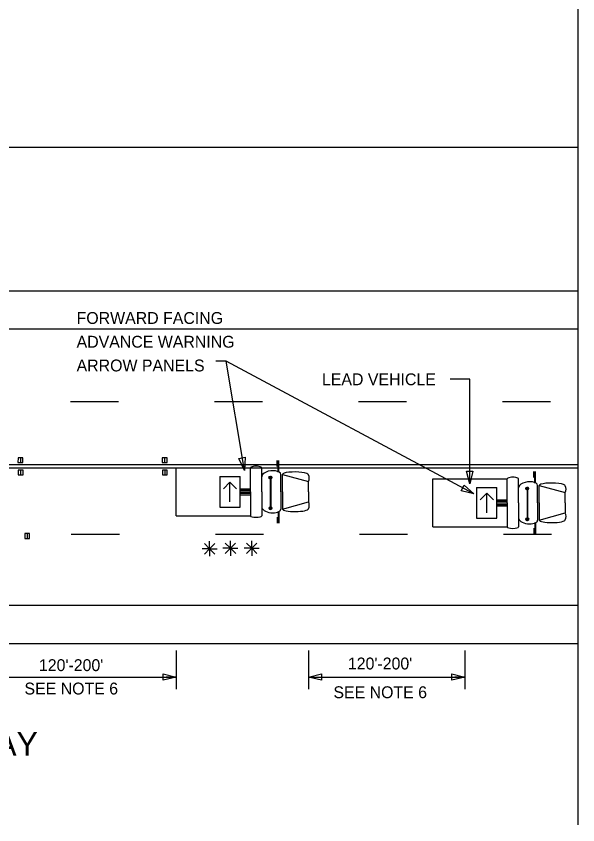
# Model space of a CAD drawing. Extents: x 1373848 to 1374003, y 380642 to 381248.
# Drawn here: x 1373899.76 to 1373928.12, y 380977.04 to 381017.9 of the extents above; entities that cross this region are included whole.
import ezdxf

# ---------------------------------------------------------------- set-up
doc = ezdxf.new("R2010")
doc.units = 0
doc.layers.add('Working Level 1', color=7, linetype='Continuous')

msp = doc.modelspace()

# ---------------------------------------------------------------- linework, layer by layer
at = {"layer": 'Working Level 1'}
for p, q in [((1373928.123, 381081.277), (1373928.123, 380977.045)), ((1373848.144, 381011.273), (1373928.089, 381011.273)), ((1373875.816, 381004.029), (1373928.123, 381004.029)), ((1373875.274, 381002.105), (1373928.123, 381002.105)), ((1373922.876, 380993.763), (1373910.36, 381000.464)), ((1373875.372, 380995.257), (1373928.123, 380995.257)), ((1373899.852, 380995.587), (1373899.851, 380995.344)), ((1373899.851, 380995.344), (1373900.094, 380995.344)), ((1373900.094, 380995.587), (1373899.852, 380995.587)), ((1373899.973, 380995.587), (1373899.973, 380995.344)), ((1373900.094, 380995.344), (1373900.094, 380995.587)), ((1373907.378, 380995.587), (1373907.135, 380995.587)), ((1373907.135, 380995.587), (1373907.135, 380995.344)), ((1373907.135, 380995.344), (1373907.378, 380995.344)), ((1373907.257, 380995.587), (1373907.257, 380995.344)), ((1373907.378, 380995.344), (1373907.378, 380995.587)), ((1373912.937, 380995.156), (1373912.937, 380995.453)), ((1373912.984, 380994.87), (1373912.984, 380995.453)), ((1373913.024, 380994.87), (1373913.024, 380995.453)), ((1373916.859, 380995.257), (1373928.123, 380995.257)), ((1373875.406, 380995.089), (1373928.123, 380995.089)), ((1373900.105, 380994.97), (1373899.862, 380994.97)), ((1373899.862, 380994.97), (1373899.862, 380994.727)), ((1373899.984, 380994.97), (1373899.984, 380994.727)), ((1373900.105, 380994.727), (1373900.105, 380994.97)), ((1373907.389, 380994.97), (1373907.146, 380994.97)), ((1373907.146, 380994.97), (1373907.146, 380994.727)), ((1373907.268, 380994.97), (1373907.267, 380994.727)), ((1373907.389, 380994.727), (1373907.389, 380994.97)), ((1373907.832, 380995.083), (1373911.587, 380995.083)), ((1373907.832, 380992.658), (1373907.832, 380995.083)), ((1373911.587, 380993.871), (1373911.587, 380995.083)), ((1373912.162, 380993.871), (1373912.162, 380995.083)), ((1373925.906, 380994.599), (1373925.906, 380994.895)), ((1373925.953, 380994.313), (1373925.953, 380994.895)), ((1373925.993, 380994.313), (1373925.993, 380994.895)), ((1373899.862, 380994.727), (1373900.105, 380994.727)), ((1373907.146, 380994.727), (1373907.389, 380994.727)), ((1373910.038, 380994.647), (1373911.064, 380994.647)), ((1373910.038, 380994.647), (1373910.038, 380993.095)), ((1373911.064, 380993.095), (1373911.064, 380994.647)), ((1373912.528, 380994.608), (1373912.528, 380994.608)), ((1373912.59, 380994.573), (1373912.59, 380993.068)), ((1373912.594, 380994.573), (1373912.594, 380993.068)), ((1373912.599, 380994.573), (1373912.599, 380993.068)), ((1373912.607, 380994.573), (1373912.607, 380993.068)), ((1373912.616, 380994.659), (1373912.616, 380994.659)), ((1373912.618, 380994.573), (1373912.618, 380993.068)), ((1373913.126, 380993.871), (1373913.126, 380994.744)), ((1373913.206, 380994.744), (1373914.519, 380994.385)), ((1373913.206, 380993.871), (1373913.206, 380994.744)), ((1373920.801, 380994.526), (1373924.556, 380994.526)), ((1373920.801, 380992.1), (1373920.801, 380994.526)), ((1373924.556, 380993.313), (1373924.556, 380994.526)), ((1373925.131, 380993.313), (1373925.131, 380994.526)), ((1373910.551, 380994.351), (1373910.221, 380994.021)), ((1373910.551, 380993.358), (1373910.551, 380994.351)), ((1373910.551, 380994.351), (1373910.888, 380994.013)), ((1373911.064, 380994.026), (1373911.587, 380994.026)), ((1373914.519, 380993.871), (1373914.519, 380994.385)), ((1373923.007, 380994.09), (1373924.033, 380994.09)), ((1373923.007, 380994.09), (1373923.007, 380992.537)), ((1373924.033, 380992.537), (1373924.033, 380994.09)), ((1373925.497, 380994.051), (1373925.497, 380994.051)), ((1373925.559, 380994.016), (1373925.559, 380992.51)), ((1373925.563, 380994.016), (1373925.563, 380992.51)), ((1373925.568, 380994.016), (1373925.568, 380992.51)), ((1373925.576, 380994.016), (1373925.576, 380992.51)), ((1373925.585, 380994.101), (1373925.585, 380994.101)), ((1373925.587, 380994.016), (1373925.587, 380992.51)), ((1373926.095, 380993.313), (1373926.095, 380994.187)), ((1373926.175, 380994.187), (1373927.488, 380993.828)), ((1373926.175, 380993.313), (1373926.175, 380994.187)), ((1373911.064, 380993.948), (1373911.587, 380993.948)), ((1373911.064, 380993.871), (1373911.587, 380993.871)), ((1373911.064, 380993.793), (1373911.587, 380993.793)), ((1373911.064, 380993.716), (1373911.587, 380993.716)), ((1373911.587, 380993.871), (1373911.587, 380992.658)), ((1373912.162, 380993.871), (1373912.162, 380992.658)), ((1373913.126, 380993.871), (1373913.126, 380992.997)), ((1373913.206, 380993.871), (1373913.206, 380992.997)), ((1373914.519, 380993.871), (1373914.519, 380993.356)), ((1373923.52, 380993.793), (1373923.19, 380993.464)), ((1373923.52, 380992.8), (1373923.52, 380993.793)), ((1373923.52, 380993.793), (1373923.857, 380993.456)), ((1373927.488, 380993.313), (1373927.488, 380993.828)), ((1373913.206, 380992.997), (1373914.519, 380993.356)), ((1373924.033, 380993.468), (1373924.556, 380993.468)), ((1373924.033, 380993.391), (1373924.556, 380993.391)), ((1373924.033, 380993.313), (1373924.556, 380993.313)), ((1373924.033, 380993.236), (1373924.556, 380993.236)), ((1373924.556, 380993.313), (1373924.556, 380992.101)), ((1373925.131, 380993.313), (1373925.131, 380992.101)), ((1373926.095, 380993.313), (1373926.095, 380992.44)), ((1373926.175, 380993.313), (1373926.175, 380992.44)), ((1373927.488, 380993.313), (1373927.488, 380992.799)), ((1373910.038, 380993.095), (1373911.064, 380993.095)), ((1373912.533, 380993.055), (1373912.533, 380993.055)), ((1373912.62, 380993.106), (1373912.62, 380993.106)), ((1373912.984, 380992.871), (1373912.984, 380992.289)), ((1373913.024, 380992.871), (1373913.024, 380992.289)), ((1373924.033, 380993.158), (1373924.556, 380993.158)), ((1373926.175, 380992.44), (1373927.488, 380992.799)), ((1373907.832, 380992.658), (1373911.587, 380992.658)), ((1373912.937, 380992.586), (1373912.937, 380992.289)), ((1373923.007, 380992.537), (1373924.033, 380992.537)), ((1373925.502, 380992.497), (1373925.502, 380992.497)), ((1373925.589, 380992.548), (1373925.589, 380992.548)), ((1373920.801, 380992.101), (1373924.556, 380992.101)), ((1373925.906, 380992.028), (1373925.906, 380991.731)), ((1373925.953, 380992.314), (1373925.953, 380991.731)), ((1373925.993, 380992.314), (1373925.993, 380991.731)), ((1373900.437, 380991.761), (1373900.194, 380991.761)), ((1373900.194, 380991.761), (1373900.194, 380991.518)), ((1373900.316, 380991.761), (1373900.315, 380991.518)), ((1373900.437, 380991.518), (1373900.437, 380991.761)), ((1373900.194, 380991.518), (1373900.437, 380991.518)), ((1373909.528, 380990.992), (1373909.262, 380991.258)), ((1373909.521, 380990.987), (1373909.788, 380991.253)), ((1373909.528, 380990.992), (1373909.528, 380991.368)), ((1373910.578, 380991.016), (1373910.312, 380991.282)), ((1373910.571, 380991.011), (1373910.838, 380991.277)), ((1373910.578, 380991.016), (1373910.578, 380991.392)), ((1373911.652, 380991.016), (1373911.386, 380991.282)), ((1373911.645, 380991.011), (1373911.912, 380991.277)), ((1373911.652, 380991.016), (1373911.652, 380991.392)), ((1373909.528, 380990.992), (1373909.151, 380990.992)), ((1373909.528, 380990.992), (1373909.262, 380990.726)), ((1373909.528, 380990.992), (1373909.794, 380990.726)), ((1373909.528, 380990.992), (1373909.528, 380990.616)), ((1373909.528, 380990.992), (1373909.904, 380990.992)), ((1373910.578, 380991.016), (1373910.201, 380991.016)), ((1373910.578, 380991.016), (1373910.312, 380990.75)), ((1373910.578, 380991.016), (1373910.844, 380990.75)), ((1373910.578, 380991.016), (1373910.578, 380990.64)), ((1373910.578, 380991.016), (1373910.954, 380991.016)), ((1373911.652, 380991.016), (1373911.275, 380991.016)), ((1373911.652, 380991.016), (1373911.386, 380990.75)), ((1373911.652, 380991.016), (1373911.918, 380990.75)), ((1373911.652, 380991.016), (1373911.652, 380990.64)), ((1373911.652, 380991.016), (1373912.028, 380991.016)), ((1373848.118, 380988.139), (1373928.123, 380988.139)), ((1373848.118, 380986.201), (1373928.123, 380986.201)), ((1373907.836, 380985.853), (1373907.836, 380983.906)), ((1373914.522, 380985.853), (1373914.522, 380983.906)), ((1373922.411, 380985.853), (1373922.411, 380983.906)), ((1373897.891, 380984.513), (1373907.836, 380984.513)), ((1373914.522, 380984.513), (1373915.073, 380984.513)), ((1373914.522, 380984.513), (1373922.411, 380984.513))]:
    msp.add_line(p, q, dxfattribs=at)
for points in [[(1373911.287, 380994.953), (1373910.36, 381000.464), (1373909.841, 381000.464)], [(1373922.662, 380994.266), (1373922.662, 380999.553), (1373921.682, 380999.553)], [(1373902.5, 380998.431), (1373904.925, 380998.431)], [(1373909.775, 380998.431), (1373912.201, 380998.431)], [(1373917.051, 380998.431), (1373919.476, 380998.431)], [(1373924.326, 380998.431), (1373926.752, 380998.431)], [(1373912.526, 380994.582), (1373912.553, 380994.536)], [(1373912.528, 380994.608), (1373912.577, 380994.523)], [(1373912.534, 380994.626), (1373912.596, 380994.52)], [(1373912.543, 380994.64), (1373912.612, 380994.521)], [(1373912.554, 380994.65), (1373912.626, 380994.526)], [(1373912.566, 380994.658), (1373912.639, 380994.532)], [(1373912.581, 380994.662), (1373912.65, 380994.542)], [(1373912.596, 380994.666), (1373912.66, 380994.555)], [(1373912.614, 380994.663), (1373912.667, 380994.571)], [(1373912.635, 380994.655), (1373912.671, 380994.594)], [(1373925.495, 380994.024), (1373925.522, 380993.979)], [(1373925.497, 380994.051), (1373925.546, 380993.966)], [(1373925.503, 380994.069), (1373925.565, 380993.962)], [(1373925.512, 380994.082), (1373925.581, 380993.964)], [(1373925.523, 380994.092), (1373925.595, 380993.968)], [(1373925.535, 380994.101), (1373925.608, 380993.975)], [(1373925.55, 380994.105), (1373925.619, 380993.985)], [(1373925.565, 380994.108), (1373925.629, 380993.997)], [(1373925.583, 380994.106), (1373925.636, 380994.014)], [(1373925.604, 380994.098), (1373925.64, 380994.037)], [(1373912.531, 380993.029), (1373912.557, 380992.983)], [(1373912.533, 380993.055), (1373912.581, 380992.97)], [(1373912.539, 380993.073), (1373912.6, 380992.967)], [(1373912.548, 380993.087), (1373912.616, 380992.968)], [(1373912.558, 380993.097), (1373912.63, 380992.973)], [(1373912.57, 380993.105), (1373912.643, 380992.979)], [(1373912.585, 380993.109), (1373912.654, 380992.989)], [(1373912.6, 380993.112), (1373912.664, 380993.002)], [(1373912.618, 380993.11), (1373912.671, 380993.018)], [(1373912.64, 380993.102), (1373912.675, 380993.041)], [(1373925.5, 380992.471), (1373925.526, 380992.425)], [(1373925.502, 380992.497), (1373925.55, 380992.413)], [(1373925.508, 380992.516), (1373925.569, 380992.409)], [(1373925.517, 380992.529), (1373925.585, 380992.411)], [(1373925.527, 380992.539), (1373925.599, 380992.415)], [(1373925.539, 380992.547), (1373925.612, 380992.422)], [(1373925.554, 380992.551), (1373925.623, 380992.431)], [(1373925.569, 380992.555), (1373925.633, 380992.444)], [(1373925.587, 380992.553), (1373925.64, 380992.46)], [(1373925.609, 380992.545), (1373925.644, 380992.483)], [(1373902.543, 380991.733), (1373904.969, 380991.733)], [(1373909.819, 380991.733), (1373912.244, 380991.733)], [(1373917.094, 380991.733), (1373919.52, 380991.733)], [(1373924.37, 380991.733), (1373926.795, 380991.733)], [(1373907.836, 380984.513), (1373907.333, 380984.513), (1373907.333, 380984.477)], [(1373922.411, 380984.513), (1373921.909, 380984.513), (1373921.909, 380984.477)]]:
    msp.add_lwpolyline(points, dxfattribs=at)
for points in [[(1373911.318, 380995.622), (1373911.287, 380994.953), (1373911, 380995.558)], [(1373922.824, 380994.916), (1373922.662, 380994.266), (1373922.499, 380994.916)], [(1373922.379, 380994.213), (1373922.876, 380993.763), (1373922.226, 380993.926)], [(1373907.186, 380984.675), (1373907.836, 380984.513), (1373907.186, 380984.35)], [(1373915.172, 380984.35), (1373914.522, 380984.513), (1373915.172, 380984.675)], [(1373921.761, 380984.675), (1373922.411, 380984.513), (1373921.761, 380984.35)]]:
    msp.add_lwpolyline(points, close=True, dxfattribs=at)
for centre in [(1373912.598, 380994.593), (1373925.567, 380994.035), (1373912.602, 380993.04), (1373925.571, 380992.482)]:
    msp.add_circle(centre, 0.0728, dxfattribs=at)
for centre in [(1373914.197, 380994.557), (1373927.166, 380993.999), (1373914.197, 380993.184), (1373927.166, 380992.627)]:
    msp.add_arc(centre, 0.364, 331.8801, 28.1199, dxfattribs=at)
for centre, major_axis, ratio, start_param, end_param in [((1373911.874, 380995.083), (0.288, 0), 0.269913, 0, 3.141593), ((1373912.643, 380994.685), (0.482, 0.06), 0.503092, 0, 3.141593), ((1373913.862, 380994.737), (0.656, -0.008), 0.2034, 0, 3.141593), ((1373924.843, 380994.526), (0.288, 0), 0.269913, 0, 3.141593), ((1373925.613, 380994.127), (0.482, 0.06), 0.503092, 0, 3.141593), ((1373926.831, 380994.179), (0.656, -0.008), 0.2034, 0, 3.141593), ((1373912.643, 380993.057), (0.482, -0.06), 0.503092, 3.141593, 6.283185), ((1373913.862, 380993.005), (0.656, 0.008), 0.2034, 3.141593, 6.283185), ((1373911.874, 380992.658), (0.288, 0), 0.269913, 3.141593, 6.283185), ((1373925.613, 380992.499), (0.482, -0.06), 0.503092, 3.141593, 6.283185), ((1373926.831, 380992.447), (0.656, 0.008), 0.2034, 3.141593, 6.283185), ((1373924.843, 380992.101), (0.288, 0), 0.269913, 3.141593, 6.283185)]:
    msp.add_ellipse(centre, major_axis=major_axis, ratio=ratio, start_param=start_param, end_param=end_param, dxfattribs=at)

# ---------------------------------------------------------------- texts
for s, p in [('FORWARD FACING', (1373902.81, 381002.351)), ('ADVANCE WARNING ', (1373902.81, 381001.151)), ('ARROW PANELS', (1373902.81, 380999.951)), ('LEAD VEHICLE', (1373915.201, 380999.253)), ("120'-200'", (1373900.908, 380984.812)), ("120'-200'", (1373916.511, 380984.895)), ('SEE NOTE 6', (1373900.178, 380983.63)), ('SEE NOTE 6', (1373915.781, 380983.443))]:
    msp.add_text(s, height=0.6, dxfattribs=at).set_placement(p)
msp.add_text('UNDIVIDED MULTILANE HIGHWAY', height=1.2, rotation=0, dxfattribs=at).set_placement((1373874.46, 380980.531))

doc.saveas('drawing.dxf')
